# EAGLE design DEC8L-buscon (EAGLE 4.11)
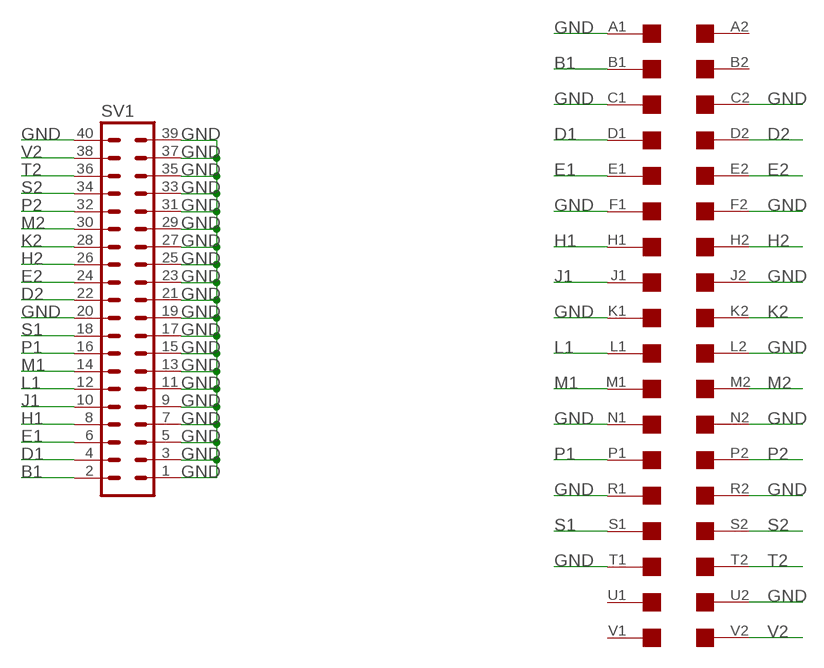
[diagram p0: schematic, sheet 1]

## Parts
SV1  MA20-2  [MA20-2]
U$1  DEC-FLIPCHIP  [DEC-FLIPCHIP]

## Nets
B1: SV1.2 U$1.B1
D1: SV1.4 U$1.D1
D2: SV1.22 U$1.D2
E1: SV1.6 U$1.E1
E2: SV1.24 U$1.E2
GND: SV1.1 SV1.3 SV1.5 SV1.7 SV1.9 SV1.11 SV1.13 SV1.15 SV1.17 SV1.19 SV1.20 SV1.21 SV1.23 SV1.25 SV1.27 SV1.29 SV1.31 SV1.33 SV1.35 SV1.37 SV1.39 SV1.40 U$1.A1 U$1.C1 U$1.C2 U$1.F1 U$1.F2 U$1.J2 U$1.K1 U$1.L2 U$1.N1 U$1.N2 U$1.R1 U$1.R2 U$1.T1 U$1.U2
H1: SV1.8 U$1.H1
H2: SV1.26 U$1.H2
J1: SV1.10 U$1.J1
K2: SV1.28 U$1.K2
L1: SV1.12 U$1.L1
M1: SV1.14 U$1.M1
M2: SV1.30 U$1.M2
P1: SV1.16 U$1.P1
P2: SV1.32 U$1.P2
S1: SV1.18 U$1.S1
S2: SV1.34 U$1.S2
T2: SV1.36 U$1.T2
V2: SV1.38 U$1.V2
Unconnected: U$1.A2 U$1.B2 U$1.U1 U$1.V1

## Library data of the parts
SV1 = con-lstb:MA20-2: PIN HEADER
U$1 = con-dec:DEC-FLIPCHIP: DEC Flip-Chip single card fingers

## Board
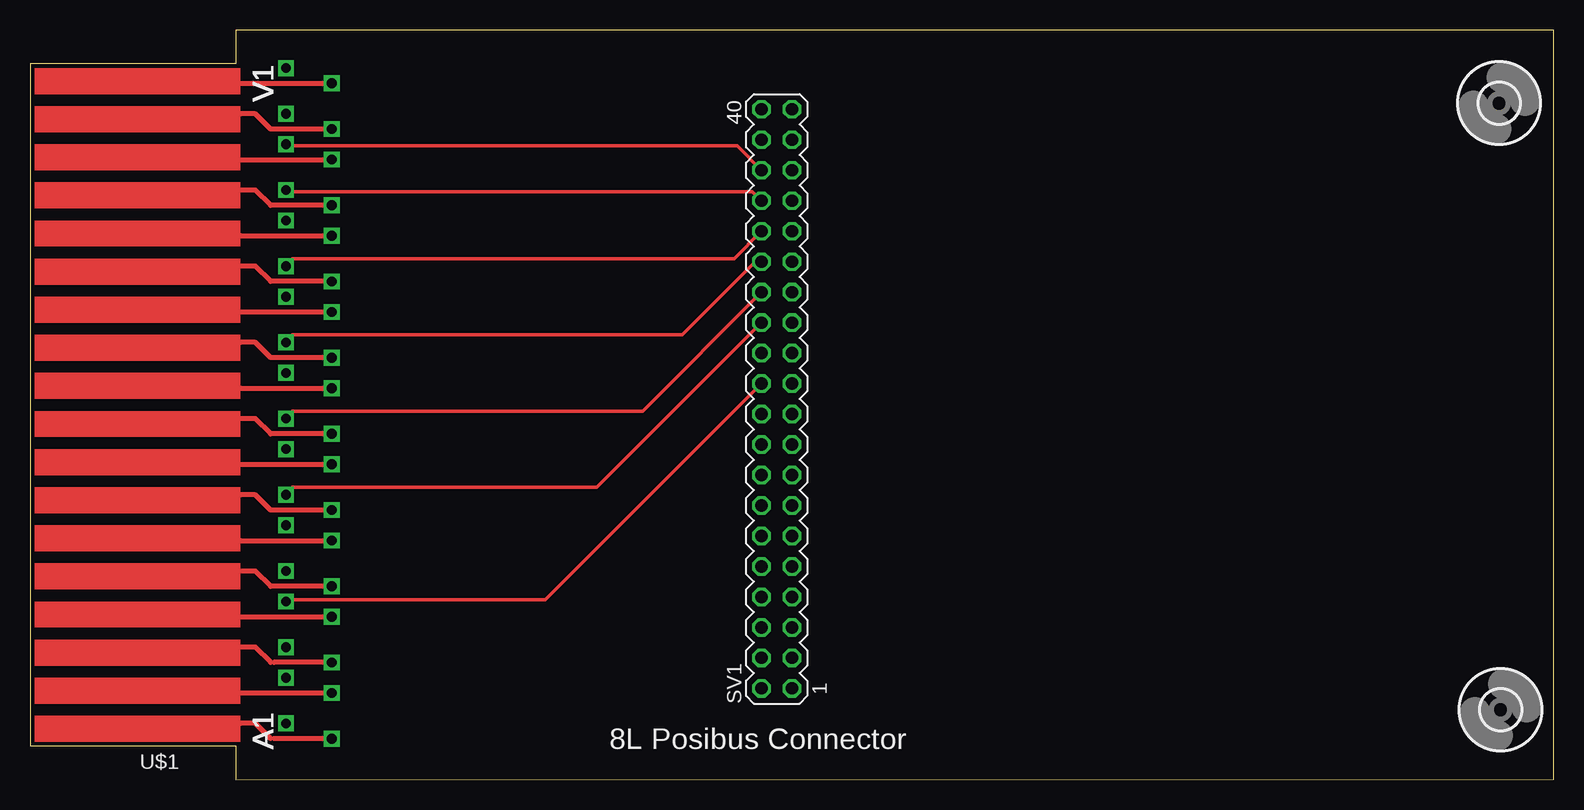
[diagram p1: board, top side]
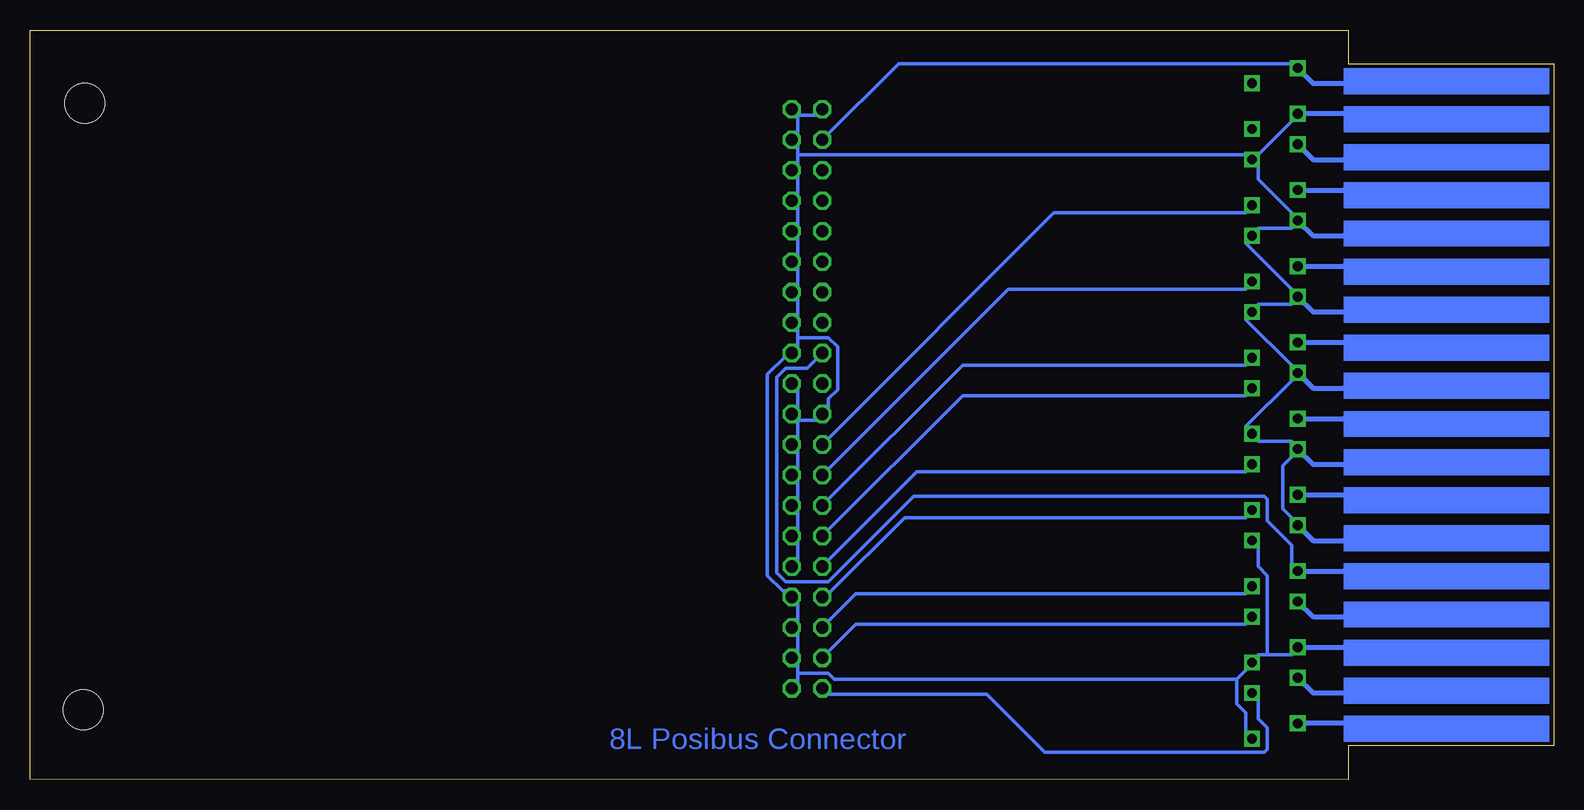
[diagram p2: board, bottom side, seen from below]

Size 126.98 x 62.48 mm. Coordinates in mm from the lower left corner, seen from the top.
Outline: 0,2.83 17.14,2.83 17.14,0 126.98,0.04 126.98,62.45 17.14,62.48 17.14,59.65 0,59.65 0,2.83
Copper layers (1*16): Top 0.035mm / dielectric 1.5mm / Bottom 0.035mm
Design rules "10mils": minimum track width 12mil, minimum drill 28mil, track to track 10mil, track to pad 10mil, pad to pad 10mil, via to via 10mil, smd to smd 10mil, copper to edge 40mil, drill to drill 10mil, minimum pad ring 10mil, minimum via ring 8mil, stop-mask expansion 0mil, vias tented up to drill 0mil, thermal gap 10mil

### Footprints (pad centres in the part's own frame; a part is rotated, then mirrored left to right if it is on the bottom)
MA20-2 = drill 1.016 octagon: 1 -24.13,-1.27; 2 -24.13,1.27; 3 -21.59,-1.27; 4 -21.59,1.27; 5 -19.05,-1.27; 6 -19.05,1.27; 7 -16.51,-1.27; 8 -16.51,1.27; 9 -13.97,-1.27; 10 -13.97,1.27; 11 -11.43,-1.27; 12 -11.43,1.27; 13 -8.89,-1.27; 14 -8.89,1.27; 15 -6.35,-1.27; 16 -6.35,1.27; 17 -3.81,-1.27; 18 -3.81,1.27; 19 -1.27,-1.27; 20 -1.27,1.27; 21 1.27,-1.27; 22 1.27,1.27; 23 3.81,-1.27; 24 3.81,1.27; 25 6.35,-1.27; 26 6.35,1.27; 27 8.89,-1.27; 28 8.89,1.27; 29 11.43,-1.27; 30 11.43,1.27; 31 13.97,-1.27; 32 13.97,1.27; 33 16.51,-1.27; 34 16.51,1.27; 35 19.05,-1.27; 36 19.05,1.27; 37 21.59,-1.27; 38 21.59,1.27; 39 24.13,-1.27; 40 24.13,1.27
DEC-FLIPCHIP = drill 0.813 square: A1 -7.62,27.94; A2 -3.81,26.67; B1 -7.62,24.13; B2 -3.81,22.86; C1 -7.62,21.59; C2 -3.81,20.32; D1 -7.62,17.78; D2 -3.81,16.51; E1 -7.62,15.24; E2 -3.81,13.97; F1 -7.62,11.43; F2 -3.81,10.16; H1 -7.62,8.89; H2 -3.81,7.62; J1 -7.62,5.08; J2 -3.81,3.81; K1 -7.62,2.54; K2 -3.81,1.27; L1 -7.62,-1.27; L2 -3.81,-2.54; M1 -7.62,-3.81; M2 -3.81,-5.08; N1 -7.62,-7.62; N2 -3.81,-8.89; P1 -7.62,-10.16; P2 -3.81,-11.43; R1 -7.62,-13.97; R2 -3.81,-15.24; S1 -7.62,-16.51; S2 -3.81,-17.78; T1 -7.62,-20.32; T2 -3.81,-21.59; U1 -7.62,-22.86; U2 -3.81,-24.13; V1 -7.62,-26.67; V2 -3.81,-27.94
3,3 = hole 3.3: 0,0

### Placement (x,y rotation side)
SV1  62.22,31.75 90 top
U$1  17.52,31.37 180 top
U$2  [3,3]  122.42,56.39 0 top
U$3  [3,3]  122.55,5.84 0 top

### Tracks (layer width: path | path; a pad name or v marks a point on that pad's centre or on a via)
B1
  Bottom 0.305: U$1.B1 24.63,6.6 24.63,5.08 23.87,4.32 23.87,2.54 24.12,2.29 42.41,2.29 47.24,7.11 60.45,7.11 SV1.2
D1
  Bottom 0.305: U$1.D1 25.65,12.95 58.16,12.95 SV1.4
D2
  Top 0.305: U$1.D2 21.84,14.99 42.92,14.99 SV1.22
E1
  Bottom 0.305: U$1.E1 25.65,15.49 58.16,15.49 SV1.6
E2
  Bottom 0.305: U$1.E2 21.84,18.03 21.84,19.56 23.87,21.59 23.87,23.37 24.12,23.62 53.34,23.62 60.45,16.51 64,16.51 64.77,17.27 64.77,33.53 64,34.29 62.22,34.29 SV1.24
GND
  Bottom 0.305: U$1.F2 21.84,21.84 22.6,22.61 22.6,26.16 21.84,26.92 U$1.J2 21.84,28.19 24.63,28.19 U$1.K1 25.65,29.46 21.84,33.27 U$1.L2 21.84,34.54 25.65,38.35 U$1.N1 24.63,39.62 21.84,39.62 U$1.N2 21.84,40.89 25.65,44.7 U$1.R1 24.63,45.97 21.84,45.97 U$1.R2 21.84,47.24 24.63,50.04 24.63,51.05 U$1.T1 | U$1.U2 21.84,54.86 24.63,52.07 U$1.T1 | 26.41,8.38 26.41,6.35 25.65,5.59 25.65,4.06 U$1.A1 | 26.41,8.38 25.65,9.14 U$1.C1 24.63,10.41 23.87,10.41 | 23.87,10.41 21.84,10.41 U$1.C2 | 23.87,10.41 23.87,17.02 24.63,17.78 24.63,19.3 U$1.F1 | 62.99,29.97 61.46,29.97 SV1.20 60.45,30.99 60.45,31.75 59.68,32.51 59.68,36.07 60.45,36.83 62.99,36.83 | SV1.21 62.99,32.51 62.99,30.99 SV1.19 62.99,29.97 | SV1.9 62.99,18.29 62.99,19.81 SV1.11 62.99,20.83 62.99,22.35 SV1.13 62.99,23.37 62.99,24.89 SV1.15 62.99,25.91 62.99,27.43 SV1.17 62.99,28.45 62.99,29.97 | 62.99,8.89 62.99,9.65 SV1.3 62.99,10.67 62.99,12.19 SV1.5 62.99,13.21 62.99,14.73 SV1.7 64,15.75 64.26,15.75 65.53,17.02 65.53,33.78 64,35.31 SV1.23 62.99,36.07 62.99,36.83 | 62.99,8.89 62.99,8.13 SV1.1 | 62.99,55.37 61.46,55.37 SV1.40 | 62.99,36.83 62.99,37.59 SV1.25 62.99,38.61 62.99,40.13 SV1.27 62.99,41.15 62.99,42.67 SV1.29 62.99,43.69 62.99,45.21 SV1.31 62.99,46.23 62.99,47.75 SV1.33 62.99,48.77 62.99,50.29 SV1.35 62.99,51.31 62.99,52.07 | 62.99,52.07 62.99,52.83 SV1.37 62.99,53.85 62.99,55.37 | 62.99,55.37 SV1.39 | 26.41,8.38 59.94,8.38 60.45,8.89 62.99,8.89 | 62.99,52.07 25.65,52.07 U$1.T1
H1
  Bottom 0.305: U$1.H1 25.65,21.84 54.1,21.84 60.45,15.49 SV1.8
H2
  Top 0.305: U$1.H2 21.84,24.38 47.24,24.38 SV1.26
J1
  Bottom 0.305: U$1.J1 25.65,25.65 53.08,25.65 SV1.10
K2
  Top 0.305: U$1.K2 21.84,30.73 51.05,30.73 SV1.28
L1
  Bottom 0.305: U$1.L1 25.65,32 49.27,32 SV1.12
M1
  Bottom 0.305: U$1.M1 25.65,34.54 49.27,34.54 SV1.14
M2
  Top 0.305: U$1.M2 21.84,37.08 54.35,37.08 60.45,43.18 SV1.30
P1
  Bottom 0.305: U$1.P1 25.65,40.89 45.46,40.89 SV1.16
P2
  Top 0.305: U$1.P2 21.84,43.43 58.67,43.43 SV1.32
S1
  Bottom 0.305: U$1.S1 25.65,47.24 41.65,47.24 SV1.18
S2
  Top 0.305: U$1.S2 21.84,49.02 60.19,49.02 SV1.34
T2
  Top 0.305: U$1.T2 21.84,52.83 58.92,52.83 SV1.36
V2
  Bottom 0.305: U$1.V2 21.84,59.69 54.6,59.69 SV1.38

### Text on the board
Bottom: 8L Posibus Connector
tPlace: 8L Posibus Connector
tNames: V1 | V1 | V1 | V1 | V1 | V1 | V1 | V1 | V1 | V1 | V1 | V1 | V1 | V1 | V1 | V1 | V1 | V1 | V1 | V1 | V1 | V1 | V1 | V1 | V1 | V1 | V1 | V1 | V1 | V1 | V1 | V1 | A1 | A1 | A1 | A1 | A1 | A1 | A1 | A1 | A1 | A1 | A1 | A1 | A1 | A1 | A1 | A1 | A1 | A1 | A1 | A1 | A1 | A1 | A1 | A1 | A1 | A1 | A1 | A1 | A1 | A1 | A1 | A1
